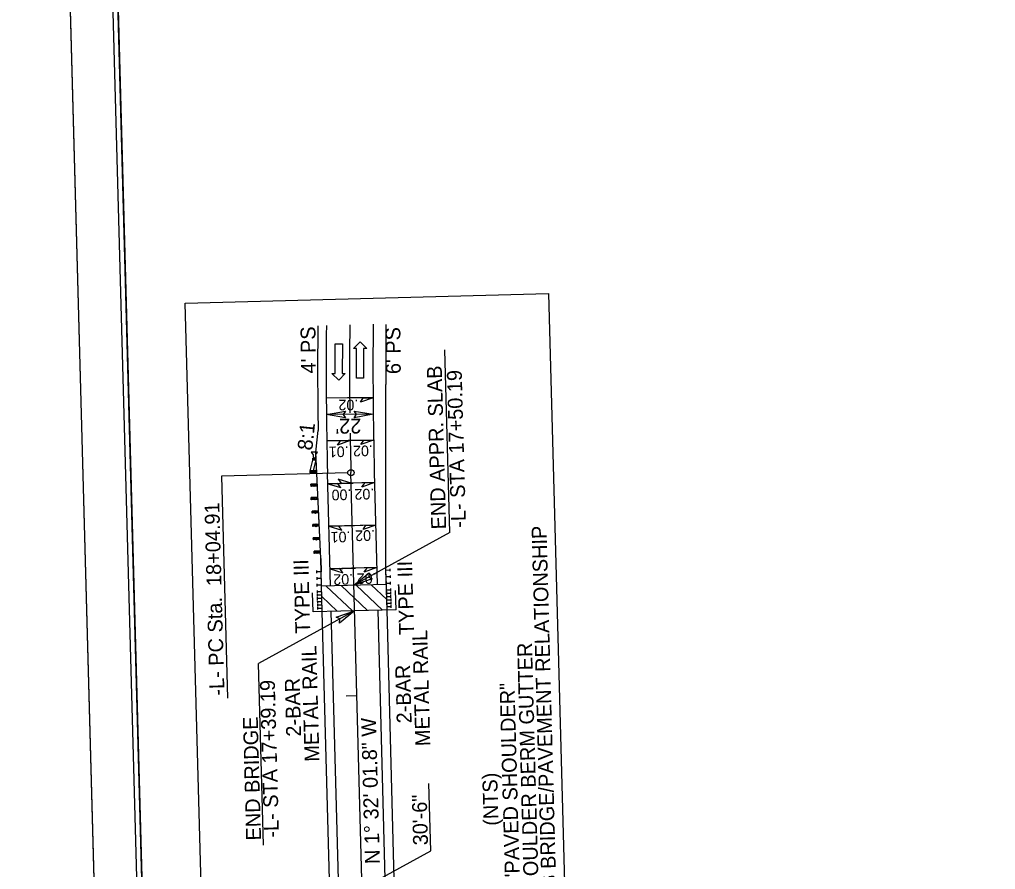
# Model space of a CAD drawing. Extents: x 1835283 to 1836442, y 993567 to 997230.
# Drawn here: x 1835301.2 to 1835759.8, y 994075.4 to 994474.7 of the extents above; entities that cross this region are included whole.
import ezdxf

# ---------------------------------------------------------------- set-up
doc = ezdxf.new("R2010")
doc.units = 0
for name, color, linetype in [('Prop Approach Slab', 7, 'Continuous'), ('Prop Approach Slab Hatching', 7, 'Continuous'), ('Prop Dimension', 7, 'Continuous'), ('Prop EOT', 7, 'Continuous'), ('Prop Guardrail', 7, 'Continuous'), ('Prop Guardrail Anchor Unit CELL', 7, 'Continuous'), ('Prop Horizontal Alignment', 7, 'Continuous'), ('Prop Horizontal Alignment Direction Label', 7, 'Continuous'), ('Prop Horizontal Alignment Station Label', 7, 'Continuous'), ('Prop Horizontal Alignment Tick Small', 7, 'Continuous'), ('Prop Lane Arrow CELL', 7, 'Continuous'), ('Prop Lane Lines', 7, 'Continuous'), ('Prop Paved Shoulder', 7, 'Continuous'), ('Prop Roadway Bridge', 7, 'Continuous'), ('Prop Structure Anchor Unit CELL', 7, 'Continuous'), ('Prop Superelevation  Arrow CELL', 7, 'Continuous'), ('Prop Superelevation Label', 7, 'Continuous'), ('Prop Terminator CELL', 7, 'Continuous'), ('Sheet Clip Boundary CELL', 7, 'Continuous'), ('Sheet Cutting Line CELL', 7, 'Continuous'), ('Sheet Layout Plan Border', 7, 'Continuous'), ('Sheet Plan CELL', 7, 'Continuous'), ('Sheet Plan Layout CELL', 7, 'Continuous'), ('Sheet Plot Border Inside CELL', 7, 'Continuous'), ('Sheet Plot Border Outside CELL', 7, 'Continuous')]:
    doc.layers.add(name, color=color, linetype=linetype)

msp = doc.modelspace()

# ---------------------------------------------------------------- linework, layer by layer
at = {"layer": 'Prop Approach Slab'}
for p, q in [((1835473.6, 994209.34), (1835443.11, 994208.53)), ((1835443.44, 994196.53), (1835443.11, 994208.53)), ((1835473.92, 994197.35), (1835473.6, 994209.34))]:
    msp.add_line(p, q, dxfattribs=at)
at = {"layer": 'Prop Approach Slab Hatching'}
for p, q in [((1835445.28, 994208.58), (1835457.61, 994196.91)), ((1835452.35, 994208.77), (1835464.68, 994197.1)), ((1835459.42, 994208.96), (1835471.75, 994197.29)), ((1835466.49, 994209.15), (1835473.79, 994202.24)), ((1835443.25, 994203.62), (1835450.53, 994196.72))]:
    msp.add_line(p, q, dxfattribs=at)
at = {"layer": 'Prop Dimension'}
for p, q in [((1835503.36, 994233.67), (1835501.01, 994319.51)), ((1835467.42, 994289.32), (1835445.42, 994289.07)), ((1835503.36, 994233.67), (1835458.36, 994208.93)), ((1835458.68, 994196.94), (1835413.58, 994172.14)), ((1835415.91, 994086.87), (1835413.58, 994172.14)), ((1835494.43, 994084.16), (1835493.57, 994115.85)), ((1835462.17, 994066.44), (1835494.43, 994084.16))]:
    msp.add_line(p, q, dxfattribs=at)
msp.add_lwpolyline([(1835549.77, 994346.04), (1835562.69, 993873.01), (1835392.04, 993868.35), (1835379.12, 994341.38)], close=True, dxfattribs=at)
at = {"layer": 'Prop EOT'}
for p, q in [((1835447.36, 994208.64), (1835445.95, 994261.53)), ((1835469.35, 994209.23), (1835467.94, 994262.12))]:
    msp.add_line(p, q, dxfattribs=at)
for radius, start in [(1821, 179.34949), (1799, 179.32239)]:
    msp.add_arc((1837266.29, 994310.27), radius, start, 181.53384, dxfattribs=at)
at = {"layer": 'Prop Guardrail'}
for p, q in [((1835473.42, 994216.09), (1835473.29, 994303.23)), ((1835442.77, 994221.52), (1835442.93, 994215.27))]:
    msp.add_line(p, q, dxfattribs=at)
msp.add_arc((1837266.27, 994311.08), 1793, 179.34819, 180.25074, dxfattribs=at)
at = {"layer": 'Prop Guardrail Anchor Unit CELL'}
for p, q in [((1835441.27, 994271.5), (1835438.33, 994271.41)), ((1835438.33, 994271.41), (1835439.22, 994270.26)), ((1835440.56, 994268.72), (1835439.06, 994268.65)), ((1835439.11, 994267.65), (1835439.06, 994268.65)), ((1835439.06, 994268.65), (1835440.6, 994267.72)), ((1835439.11, 994267.65), (1835439.08, 994268.15)), ((1835440.56, 994268.72), (1835439.11, 994267.65)), ((1835439.22, 994270.26), (1835439.28, 994268.21)), ((1835439.28, 994268.21), (1835439.89, 994268.23)), ((1835439.89, 994268.23), (1835440.5, 994268.25)), ((1835440.45, 994270.3), (1835441.27, 994271.5)), ((1835440.5, 994268.25), (1835440.45, 994270.3)), ((1835442.77, 994221.52), (1835440.58, 994268.22)), ((1835437.77, 994262.68), (1835439.11, 994267.65)), ((1835440.6, 994267.72), (1835439.11, 994267.65)), ((1835439.3, 994262.76), (1835440.6, 994267.72)), ((1835440.83, 994262.83), (1835437.77, 994262.68)), ((1835437.82, 994261.68), (1835437.77, 994262.68)), ((1835437.77, 994262.68), (1835439.35, 994261.76)), ((1835439.3, 994262.76), (1835437.82, 994261.68)), ((1835440.88, 994261.83), (1835437.82, 994261.68)), ((1835439.35, 994261.76), (1835439.3, 994262.76)), ((1835440.88, 994261.83), (1835439.3, 994262.76)), ((1835439.35, 994261.76), (1835440.83, 994262.83)), ((1835441.13, 994256.53), (1835438.13, 994256.39)), ((1835438.18, 994255.39), (1835438.13, 994256.39)), ((1835438.13, 994256.39), (1835439.68, 994255.46)), ((1835439.63, 994256.46), (1835438.18, 994255.39)), ((1835441.17, 994255.53), (1835438.18, 994255.39)), ((1835439.68, 994255.46), (1835439.63, 994256.46)), ((1835441.17, 994255.53), (1835439.63, 994256.46)), ((1835439.68, 994255.46), (1835441.13, 994256.53)), ((1835441.42, 994250.24), (1835438.29, 994250.09)), ((1835438.33, 994249.09), (1835438.29, 994250.09)), ((1835438.29, 994250.09), (1835439.9, 994249.16)), ((1835439.86, 994250.16), (1835438.33, 994249.09)), ((1835439.9, 994249.16), (1835439.86, 994250.16)), ((1835441.47, 994249.24), (1835439.86, 994250.16)), ((1835439.9, 994249.16), (1835441.42, 994250.24)), ((1835441.47, 994249.24), (1835438.33, 994249.09)), ((1835441.72, 994243.94), (1835438.68, 994243.8)), ((1835438.73, 994242.8), (1835438.68, 994243.8)), ((1835438.68, 994243.8), (1835440.25, 994242.87)), ((1835440.2, 994243.87), (1835438.73, 994242.8)), ((1835441.76, 994242.94), (1835438.73, 994242.8)), ((1835440.25, 994242.87), (1835440.2, 994243.87)), ((1835441.76, 994242.94), (1835440.2, 994243.87)), ((1835440.25, 994242.87), (1835441.72, 994243.94)), ((1835441.76, 994242.94), (1835441.72, 994243.94)), ((1835442.01, 994237.65), (1835438.97, 994237.51)), ((1835439.01, 994236.51), (1835438.97, 994237.51)), ((1835438.97, 994237.51), (1835440.54, 994236.58)), ((1835440.49, 994237.58), (1835439.01, 994236.51)), ((1835442.06, 994236.65), (1835439.01, 994236.51)), ((1835440.54, 994236.58), (1835440.49, 994237.58)), ((1835442.06, 994236.65), (1835440.49, 994237.58)), ((1835440.54, 994236.58), (1835442.01, 994237.65)), ((1835442.31, 994231.35), (1835439.26, 994231.21)), ((1835439.3, 994230.21), (1835439.26, 994231.21)), ((1835439.26, 994231.21), (1835440.83, 994230.28)), ((1835440.78, 994231.28), (1835439.3, 994230.21)), ((1835440.83, 994230.28), (1835440.78, 994231.28)), ((1835442.35, 994230.36), (1835440.78, 994231.28)), ((1835440.83, 994230.28), (1835442.31, 994231.35)), ((1835442.35, 994230.36), (1835439.3, 994230.21)), ((1835442.6, 994225.06), (1835439.6, 994224.92)), ((1835439.65, 994223.92), (1835439.6, 994224.92)), ((1835439.6, 994224.92), (1835441.15, 994223.99)), ((1835441.1, 994224.99), (1835439.65, 994223.92)), ((1835442.65, 994224.06), (1835439.65, 994223.92)), ((1835442.6, 994225.06), (1835441.1, 994224.99)), ((1835441.15, 994223.99), (1835441.1, 994224.99)), ((1835441.1, 994224.99), (1835442.65, 994224.06)), ((1835441.15, 994223.99), (1835442.6, 994225.06)), ((1835442.65, 994224.06), (1835442.6, 994225.06))]:
    msp.add_line(p, q, dxfattribs=at)
at = {"layer": 'Prop Horizontal Alignment'}
msp.add_line((1835462.64, 994049.02), (1835456.94, 994261.82), dxfattribs=at)
for start, end in [(179.33603, 180.64465), (180.94883, 181.53384)]:
    msp.add_arc((1837266.29, 994310.27), 1810, start, end, dxfattribs=at)
at = {"layer": 'Prop Horizontal Alignment Station Label'}
for p, q in [((1835455.44, 994261.78), (1835396.14, 994260.19)), ((1835396.14, 994260.19), (1835398.99, 994155.9))]:
    msp.add_line(p, q, dxfattribs=at)
msp.add_circle((1835456.94, 994261.82), 1.5, dxfattribs=at)
at = {"layer": 'Prop Horizontal Alignment Tick Small'}
for p, q in [((1835457.07, 994256.92), (1835452.08, 994256.78)), ((1835459.75, 994156.95), (1835454.75, 994156.82))]:
    msp.add_line(p, q, dxfattribs=at)
at = {"layer": 'Prop Lane Arrow CELL'}
for p, q in [((1835458.11, 994320.19), (1835461.21, 994323.33)), ((1835461.21, 994323.33), (1835464.41, 994320.18)), ((1835449.51, 994308.37), (1835449.61, 994322.36)), ((1835449.61, 994322.36), (1835452.91, 994322.34)), ((1835452.91, 994322.34), (1835452.81, 994308.34)), ((1835459.61, 994320.19), (1835458.11, 994320.19)), ((1835459.59, 994306.19), (1835459.61, 994320.19)), ((1835462.91, 994320.18), (1835462.89, 994306.18)), ((1835464.41, 994320.18), (1835462.91, 994320.18)), ((1835451.19, 994305.2), (1835448.01, 994308.38)), ((1835448.01, 994308.38), (1835449.51, 994308.37)), ((1835454.31, 994308.33), (1835451.19, 994305.2)), ((1835452.81, 994308.34), (1835454.31, 994308.33)), ((1835462.89, 994306.18), (1835459.59, 994306.19))]:
    msp.add_line(p, q, dxfattribs=at)
at = {"layer": 'Prop Paved Shoulder'}
for p, q in [((1835473.42, 994216.09), (1835473.29, 994303.23)), ((1835440.43, 994271.47), (1835441.52, 994281.66)), ((1835442.77, 994221.52), (1835440.43, 994271.47)), ((1835443.11, 994208.53), (1835442.77, 994221.52)), ((1835473.61, 994208.96), (1835473.42, 994216.09))]:
    msp.add_line(p, q, dxfattribs=at)
for centre, radius, start, end in [((1837266.29, 994310.27), 1825, 179.35435, 180.89838), ((1837255.56, 994311.27), 1782.29, 179.35044, 180.25842)]:
    msp.add_arc(centre, radius, start, end, dxfattribs=at)
at = {"layer": 'Prop Roadway Bridge'}
for p, q in [((1835439.19, 994196.42), (1835438.95, 994205.41)), ((1835478.17, 994197.46), (1835477.93, 994206.46)), ((1835478.17, 994197.46), (1835439.19, 994196.42)), ((1835448.52, 994006.6), (1835443.44, 994196.53)), ((1835452.77, 994006.71), (1835447.68, 994196.64)), ((1835474.76, 994007.3), (1835469.68, 994197.23)), ((1835479.01, 994007.41), (1835473.92, 994197.35))]:
    msp.add_line(p, q, dxfattribs=at)
at = {"layer": 'Prop Structure Anchor Unit CELL'}
for p, q in [((1835440.95, 994214.65), (1835440.92, 994215.79)), ((1835442.93, 994215.27), (1835440.93, 994215.22)), ((1835443.44, 994196.53), (1835442.93, 994215.27)), ((1835473.42, 994216.09), (1835475.42, 994216.14)), ((1835473.92, 994197.35), (1835473.42, 994216.09)), ((1835473.51, 994212.97), (1835475.51, 994213.02)), ((1835475.44, 994215.57), (1835475.41, 994216.72)), ((1835475.52, 994212.45), (1835475.49, 994213.59)), ((1835441.03, 994211.52), (1835441, 994212.67)), ((1835443.02, 994212.15), (1835441.02, 994212.1)), ((1835441.12, 994208.4), (1835441.09, 994209.54)), ((1835443.1, 994209.03), (1835441.1, 994208.97)), ((1835473.59, 994209.84), (1835475.59, 994209.9)), ((1835475.6, 994209.32), (1835475.57, 994210.47)), ((1835441.2, 994205.28), (1835441.17, 994206.42)), ((1835443.18, 994205.9), (1835441.19, 994205.85)), ((1835441.24, 994203.71), (1835441.21, 994204.86)), ((1835443.23, 994204.34), (1835441.23, 994204.29)), ((1835473.67, 994206.72), (1835475.67, 994206.77)), ((1835473.72, 994205.16), (1835475.71, 994205.21)), ((1835473.76, 994203.59), (1835475.76, 994203.65)), ((1835475.69, 994206.2), (1835475.66, 994207.34)), ((1835475.73, 994204.64), (1835475.7, 994205.78)), ((1835475.77, 994203.08), (1835475.74, 994204.22)), ((1835441.28, 994202.15), (1835441.25, 994203.3)), ((1835443.27, 994202.78), (1835441.27, 994202.72)), ((1835441.33, 994200.59), (1835441.3, 994201.74)), ((1835443.31, 994201.22), (1835441.31, 994201.16)), ((1835441.37, 994199.03), (1835441.34, 994200.17)), ((1835443.35, 994199.65), (1835441.35, 994199.6)), ((1835473.8, 994202.03), (1835475.8, 994202.09)), ((1835473.84, 994200.47), (1835475.84, 994200.52)), ((1835473.88, 994198.91), (1835475.88, 994198.96)), ((1835475.81, 994201.51), (1835475.78, 994202.66)), ((1835475.86, 994199.95), (1835475.82, 994201.1)), ((1835475.9, 994198.39), (1835475.87, 994199.53)), ((1835441.41, 994197.47), (1835441.38, 994198.61)), ((1835443.39, 994198.09), (1835441.39, 994198.04))]:
    msp.add_line(p, q, dxfattribs=at)
at = {"layer": 'Prop Superelevation  Arrow CELL'}
for p, q in [((1835467.34, 994296.99), (1835455.34, 994296.9)), ((1835467.6, 994277.11), (1835455.6, 994276.89)), ((1835456.6, 994276.91), (1835445.6, 994276.71)), ((1835446.08, 994256.62), (1835458.07, 994256.94)), ((1835457.07, 994256.92), (1835446.08, 994256.62)), ((1835468.07, 994257.21), (1835456.07, 994256.89)), ((1835446.61, 994236.63), (1835458.61, 994236.95)), ((1835468.61, 994237.22), (1835456.61, 994236.9)), ((1835447.15, 994216.64), (1835459.14, 994216.96)), ((1835447.15, 994216.64), (1835459.14, 994216.96)), ((1835469.14, 994217.23), (1835457.15, 994216.9))]:
    msp.add_line(p, q, dxfattribs=at)
for points in [[(1835467.34, 994296.99), (1835461.36, 994294.95), (1835462.72, 994296.96)], [(1835467.6, 994277.11), (1835461.64, 994275), (1835462.98, 994277.03)], [(1835456.6, 994276.91), (1835450.64, 994274.8), (1835451.98, 994276.83)], [(1835457.07, 994256.92), (1835451.02, 994258.76), (1835452.45, 994256.79)], [(1835446.08, 994256.62), (1835452.13, 994254.78), (1835450.7, 994256.75)], [(1835468.07, 994257.21), (1835462.13, 994255.05), (1835463.45, 994257.09)], [(1835446.61, 994236.63), (1835452.66, 994234.79), (1835451.24, 994236.75)], [(1835468.61, 994237.22), (1835462.66, 994235.06), (1835463.98, 994237.09)], [(1835447.15, 994216.64), (1835453.2, 994214.8), (1835451.77, 994216.76)], [(1835447.15, 994216.64), (1835453.2, 994214.8), (1835451.77, 994216.76)], [(1835469.14, 994217.23), (1835463.2, 994215.07), (1835464.52, 994217.1)]]:
    msp.add_lwpolyline(points, close=True, dxfattribs=at)
at = {"layer": 'Prop Superelevation Label'}
for p, q in [((1835467.34, 994296.99), (1835445.34, 994296.83)), ((1835445.6, 994276.71), (1835467.6, 994277.11)), ((1835468.07, 994257.21), (1835446.08, 994256.62)), ((1835468.61, 994237.22), (1835446.61, 994236.63)), ((1835469.14, 994217.23), (1835447.15, 994216.64))]:
    msp.add_line(p, q, dxfattribs=at)
at = {"layer": 'Prop Terminator CELL'}
for points in [[(1835454.44, 994287.62), (1835445.42, 994289.07), (1835454.45, 994290.77), (1835453.32, 994289.16)], [(1835458.4, 994290.77), (1835467.42, 994289.32), (1835458.39, 994287.62), (1835459.52, 994289.23)], [(1835466.99, 994211.91), (1835458.36, 994208.93), (1835465.52, 994214.7), (1835465.28, 994212.74)], [(1835450.05, 994193.96), (1835458.68, 994196.94), (1835451.52, 994191.18), (1835451.76, 994193.13)]]:
    msp.add_lwpolyline(points, close=True, dxfattribs=at)
at = {"layer": 'Sheet Clip Boundary CELL'}
msp.add_lwpolyline([(1836414.25, 993881.51), (1836374.18, 995348.6), (1835535.98, 995325.71), (1835542.09, 995102.18), (1835330.68, 995096.4), (1835364.64, 993852.84)], close=True, dxfattribs=at)
msp.add_lwpolyline([(1836414.25, 993881.51), (1836374.18, 995348.6), (1835535.98, 995325.71), (1835542.09, 995102.18), (1835330.68, 995096.4), (1835364.64, 993852.84)], close=True, dxfattribs=at)
at = {"layer": 'Sheet Cutting Line CELL'}
msp.add_line((1835301.2, 995351.94), (1835347.16, 993669.07), dxfattribs=at)
at = {"layer": 'Sheet Layout Plan Border'}
msp.add_lwpolyline([(1836414.25, 993881.51), (1836374.18, 995348.6), (1835535.98, 995325.71), (1835542.09, 995102.18), (1835330.68, 995096.4), (1835364.64, 993852.84)], close=True, dxfattribs=at)
msp.add_lwpolyline([(1836414.25, 993881.51), (1836374.18, 995348.6), (1835535.98, 995325.71), (1835542.09, 995102.18), (1835330.68, 995096.4), (1835364.64, 993852.84)], close=True, dxfattribs=at)
at = {"layer": 'Sheet Plan CELL'}
for points in [[(1835324.15, 995335.59), (1835365.1, 993836.11), (1836414.7, 993864.77), (1836373.75, 995364.23)], [(1836414.7, 993864.77), (1835365.12, 993836.09), (1835329.59, 995135.59), (1835479.6, 995139.7), (1835474.15, 995339.66), (1836373.75, 995364.23)]]:
    msp.add_lwpolyline(points, close=True, dxfattribs=at)
at = {"layer": 'Sheet Plan Layout CELL'}
msp.add_lwpolyline([(1835365.12, 993836.1), (1836414.7, 993864.79), (1836373.75, 995364.23), (1835535.55, 995341.34), (1835542.09, 995102.18), (1835330.68, 995096.4)], close=True, dxfattribs=at)
at = {"layer": 'Sheet Plot Border Inside CELL'}
msp.add_lwpolyline([(1836421.41, 993711.41), (1836375.91, 995376.78), (1835321.32, 995347.99), (1835366.8, 993682.61)], close=True, dxfattribs=at)
at = {"layer": 'Sheet Plot Border Outside CELL'}
msp.add_lwpolyline([(1836441.75, 993698.96), (1836395.79, 995381.84), (1835301.2, 995351.94), (1835347.16, 993669.07)], close=True, dxfattribs=at)

# ---------------------------------------------------------------- texts
at = {"layer": 'Prop Dimension'}
for s, rotation, p in [('END APPR. SLAB', 91.5643, (1835501.71, 994235.26)), ('-L- STA 17+50.19', 91.5643, (1835511.02, 994236.03)), ("22'", 180.6672, (1835461.79, 994287.25)), ('SKETCH SHOWING BRIDGE/PAVEMENT RELATIONSHIP', 91.5643, (1835555.65, 993986.91)), ('METAL RAIL', 91.5643, (1835494.24, 994133.45)), ('SBG - SHOULDER BERM GUTTER', 91.5643, (1835546.13, 994031.3)), ('METAL RAIL', 91.5643, (1835442.17, 994126.14)), ('2-BAR', 91.5643, (1835485.49, 994144.16)), ('-L- STA 17+39.19', 91.5643, (1835423.17, 994090.46)), ('2-BAR', 91.5643, (1835433.55, 994137.93)), ('PS - "PAVED SHOULDER"', 91.5643, (1835536.89, 994049.46)), ('END BRIDGE', 91.5643, (1835414.73, 994089.13)), ('(NTS)', 91.5643, (1835526.33, 994096.05)), ('30\'-6"', 91.5645, (1835493.19, 994086.85))]:
    msp.add_text(s, height=7, rotation=rotation, dxfattribs=at).set_placement(p)
at = {"layer": 'Prop Guardrail Anchor Unit CELL'}
for p in [(1835437.86, 994186.38), (1835486.61, 994185.66)]:
    msp.add_text('TYPE III', height=7, rotation=91.5645, dxfattribs=at).set_placement(p)
at = {"layer": 'Prop Horizontal Alignment Direction Label'}
msp.add_text('N 1%%d 32\' 01.8" W', height=7, rotation=91.5338, dxfattribs=at).set_placement((1835470.55, 994078.09))
at = {"layer": 'Prop Horizontal Alignment Station Label'}
msp.add_text('-L- PC Sta.  18+04.91', height=7, rotation=91.5643, dxfattribs=at).set_placement((1835397.55, 994157.17))
at = {"layer": 'Prop Lane Lines'}
for s, rotation, p in [('.02', 180.4229, (1835460.37, 994296.15)), ('.01', 181.056, (1835455.81, 994274.23)), ('.02', 181.056, (1835467.19, 994274.62)), ('.00', 181.5338, (1835457.09, 994254.04)), ('.02', 181.5338, (1835467.85, 994254.34)), ('.01', 181.5338, (1835456.64, 994234.21)), ('.02', 181.5338, (1835468.19, 994234.9)), ('.02', 181.5338, (1835457.9, 994214.3)), ('.02', 181.5338, (1835468.93, 994214.7))]:
    msp.add_text(s, height=5, rotation=rotation, dxfattribs=at).set_placement(p)
at = {"layer": 'Prop Terminator CELL'}
for s, rotation, p in [("4' PS", 90.6094, (1835440.48, 994308.46)), ("6' PS", 90.6094, (1835480.38, 994308.14)), ('8:1', 83.8907, (1835438.73, 994272.04))]:
    msp.add_text(s, height=7, rotation=rotation, dxfattribs=at).set_placement(p)

doc.saveas('drawing.dxf')
